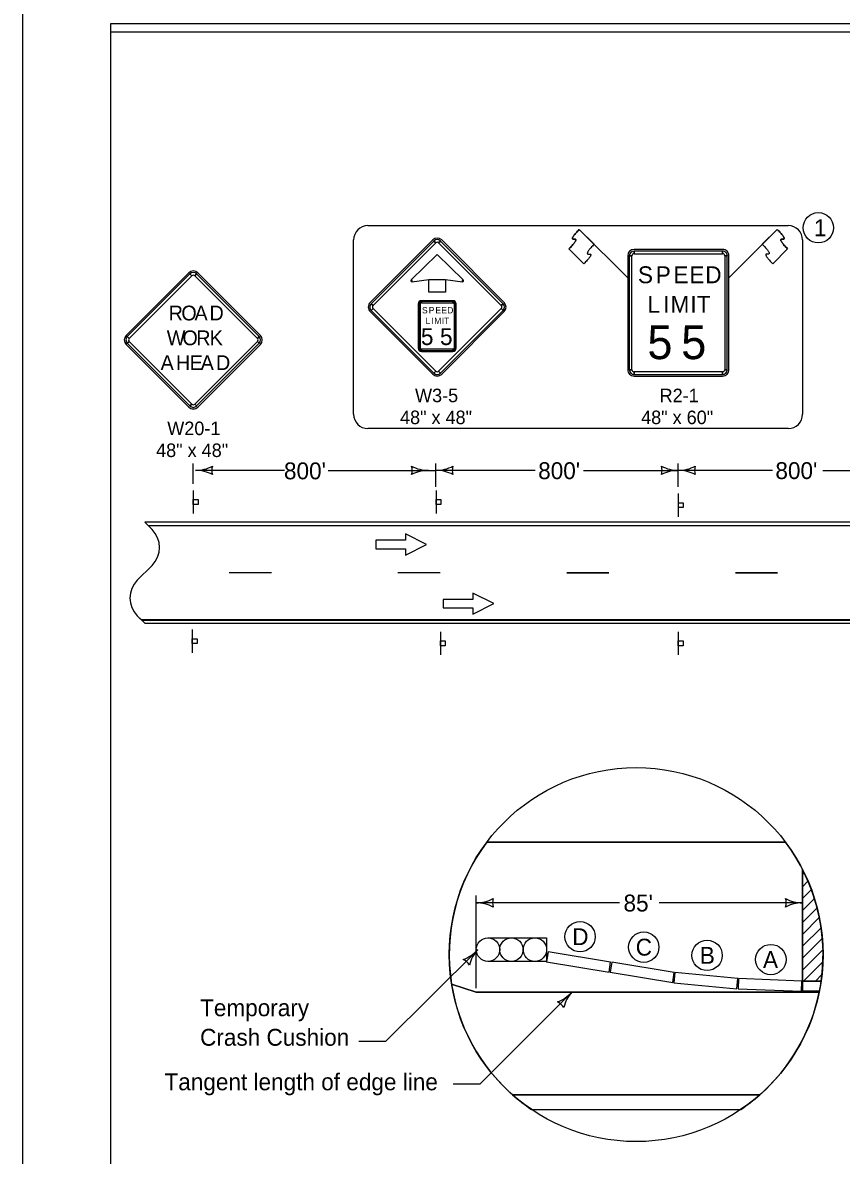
# Model space of a CAD drawing. Extents: x 10133 to 81668, y 4177 to 11018.
# Drawn here: x 24428 to 25399, y 8603 to 9945 of the extents above; entities that cross this region are included whole.
import ezdxf

# ---------------------------------------------------------------- set-up
doc = ezdxf.new("R2010")
doc.units = 0
for name, color, linetype in [('dsnNonPlotable', 7, 'Continuous'), ('dsnStdBlockModified', 7, 'Continuous'), ('dsnStdBorder', 7, 'Continuous'), ('dsnStdDimension', 7, 'Continuous'), ('dsnStdLabel', 7, 'Continuous'), ('dsnStdLineWork', 7, 'Continuous'), ('dsnStdNote', 7, 'Continuous'), ('dsnStdShading', 7, 'Continuous'), ('Level 2', 7, 'Continuous'), ('SheetBorder', 7, 'Continuous')]:
    doc.layers.add(name, color=color, linetype=linetype)

msp = doc.modelspace()

# ---------------------------------------------------------------- linework, layer by layer
at = {"layer": 'dsnNonPlotable'}
for p, q in [((25145.5, 9642.6), (25088.1, 9699.9)), ((25088.1, 9699.9), (25105.8, 9682.3)), ((25265.5, 9642.6), (25322.8, 9699.9)), ((25322.8, 9699.9), (25305.1, 9682.3)), ((24914.3, 9687.5), (24840, 9613.2)), ((24915.6, 9686.1), (24917.8, 9683.9)), ((24921.3, 9683.9), (24923.6, 9686.1)), ((24999.1, 9613.2), (24924.9, 9687.5)), ((25075.8, 9676.9), (25093.4, 9659.3)), ((25093.4, 9659.3), (25075.8, 9676.9)), ((25145.5, 9668.7), (25145.5, 9533.7)), ((25147.3, 9668.7), (25150.5, 9668.7)), ((25258, 9676.2), (25153, 9676.2)), ((25153, 9671.2), (25153, 9674.3)), ((25258, 9674.3), (25258, 9671.2)), ((25260.5, 9668.7), (25263.6, 9668.7)), ((25265.5, 9533.7), (25265.5, 9668.7)), ((25335.1, 9676.9), (25317.5, 9659.3)), ((25317.5, 9659.3), (25335.1, 9676.9)), ((24625.1, 9648.5), (24550.8, 9574.3)), ((24626.4, 9647.2), (24628.6, 9645)), ((24632.1, 9645), (24634.3, 9647.2)), ((24709.9, 9574.3), (24635.7, 9648.5)), ((24889.6, 9639.2), (24888.7, 9640.1)), ((24889.7, 9637.9), (24889.6, 9639.2)), ((24949.6, 9639.2), (24949.4, 9637.9)), ((24950.5, 9640.1), (24949.6, 9639.2)), ((24843.6, 9609.7), (24841.3, 9611.9)), ((24897.1, 9611.7), (24897.1, 9559.2)), ((24898, 9611.7), (24899.6, 9611.7)), ((24938.3, 9615.4), (24900.8, 9615.4)), ((24900.8, 9612.9), (24900.8, 9614.5)), ((24938.3, 9614.5), (24938.3, 9612.9)), ((24939.6, 9611.7), (24941.1, 9611.7)), ((24942.1, 9559.2), (24942.1, 9611.7)), ((24997.8, 9611.9), (24995.6, 9609.7)), ((24840, 9602.6), (24914.3, 9528.4)), ((24841.3, 9603.9), (24843.6, 9606.1)), ((24924.9, 9528.4), (24999.1, 9602.6)), ((24995.6, 9606.1), (24997.8, 9603.9)), ((24554.4, 9570.7), (24552.1, 9572.9)), ((24708.6, 9572.9), (24706.4, 9570.7)), ((24550.8, 9563.6), (24625.1, 9489.4)), ((24552.1, 9565), (24554.4, 9567.2)), ((24635.7, 9489.4), (24709.9, 9563.6)), ((24706.4, 9567.2), (24708.6, 9565)), ((24899.6, 9559.2), (24898, 9559.2)), ((24941.1, 9559.2), (24939.6, 9559.2)), ((24900.8, 9556.4), (24900.8, 9557.9)), ((24900.8, 9555.4), (24938.3, 9555.4)), ((24938.3, 9557.9), (24938.3, 9556.4)), ((24917.8, 9531.9), (24915.6, 9529.7)), ((24923.6, 9529.7), (24921.3, 9531.9)), ((25150.5, 9533.7), (25147.3, 9533.7)), ((25153, 9528), (25153, 9531.2)), ((25258, 9531.2), (25258, 9528)), ((25263.6, 9533.7), (25260.5, 9533.7)), ((25153, 9526.2), (25258, 9526.2)), ((24628.6, 9492.9), (24626.4, 9490.7)), ((24634.3, 9490.7), (24632.1, 9492.9)), ((24630.3, 9390.6), (24630.3, 9363.1)), ((24918.3, 9390.6), (24918.3, 9363.1)), ((25205.5, 9386.8), (25205.5, 9359.3)), ((24629.1, 9225.6), (24629.1, 9198.1)), ((24923.4, 9223.1), (24923.4, 9195.6)), ((25205.5, 9223.1), (25205.5, 9195.6))]:
    msp.add_line(p, q, dxfattribs=at)
for points in [[(24837.4, 9704.6), (25335.8, 9704.6)], [(24820.4, 9480.9), (24820.4, 9687.5)], [(25352.8, 9687.5), (25352.8, 9480.9)], [(25335.8, 9463.9), (24837.4, 9463.9)], [(24846.8, 9331.5), (24846.8, 9321.5), (24881.8, 9321.5), (24881.8, 9314), (24906.8, 9326.5), (24881.8, 9339), (24881.8, 9331.5), (24846.8, 9331.5)], [(24926.8, 9261.5), (24926.8, 9251.5), (24961.8, 9251.5), (24961.8, 9244), (24986.8, 9256.5), (24961.8, 9269), (24961.8, 9261.5), (24926.8, 9261.5)]]:
    msp.add_lwpolyline(points, dxfattribs=at)
for points in [[(24915.6, 9686.1), (24841.3, 9611.9), (24843.6, 9609.7), (24917.8, 9683.9), (24915.6, 9686.1)], [(24997.8, 9611.9), (24923.6, 9686.1), (24921.3, 9683.9), (24995.6, 9609.7), (24997.8, 9611.9)], [(24919.6, 9670.4), (24888.7, 9640.1), (24889.6, 9639.2), (24889.7, 9637.9), (24909.6, 9640.4), (24929.6, 9640.4), (24949.4, 9637.9), (24949.6, 9639.2), (24950.5, 9640.1), (24919.6, 9670.4)], [(25147.3, 9668.7), (25147.3, 9533.7), (25150.5, 9533.7), (25150.5, 9668.7), (25147.3, 9668.7)], [(25258, 9674.3), (25153, 9674.3), (25153, 9671.2), (25258, 9671.2), (25258, 9674.3)], [(25263.6, 9533.7), (25263.6, 9668.7), (25260.5, 9668.7), (25260.5, 9533.7), (25263.6, 9533.7)], [(24626.4, 9647.2), (24552.1, 9572.9), (24554.4, 9570.7), (24628.6, 9645), (24626.4, 9647.2)], [(24708.6, 9572.9), (24634.3, 9647.2), (24632.1, 9645), (24706.4, 9570.7), (24708.6, 9572.9)], [(24929.6, 9625.4), (24909.6, 9625.4), (24909.6, 9640.4), (24929.6, 9640.4), (24929.6, 9625.4)], [(24898, 9611.7), (24898, 9559.2), (24899.6, 9559.2), (24899.6, 9611.7), (24898, 9611.7)], [(24938.3, 9614.5), (24900.8, 9614.5), (24900.8, 9612.9), (24938.3, 9612.9), (24938.3, 9614.5)], [(24941.1, 9559.2), (24941.1, 9611.7), (24939.6, 9611.7), (24939.6, 9559.2), (24941.1, 9559.2)], [(24841.3, 9603.9), (24915.6, 9529.7), (24917.8, 9531.9), (24843.6, 9606.1), (24841.3, 9603.9)], [(24923.6, 9529.7), (24997.8, 9603.9), (24995.6, 9606.1), (24921.3, 9531.9), (24923.6, 9529.7)], [(24552.1, 9565), (24626.4, 9490.7), (24628.6, 9492.9), (24554.4, 9567.2), (24552.1, 9565)], [(24634.3, 9490.7), (24708.6, 9565), (24706.4, 9567.2), (24632.1, 9492.9), (24634.3, 9490.7)], [(24900.8, 9556.4), (24938.3, 9556.4), (24938.3, 9557.9), (24900.8, 9557.9), (24900.8, 9556.4)], [(25153, 9528), (25258, 9528), (25258, 9531.2), (25153, 9531.2), (25153, 9528)], [(24630.4, 9374.1), (24630.4, 9379.7), (24636, 9379.7), (24636, 9374.1)], [(24918.4, 9374.1), (24918.4, 9379.7), (24924, 9379.7), (24924, 9374.1)], [(25205.6, 9370.4), (25205.6, 9376), (25211.2, 9376), (25211.2, 9370.4)], [(24629.2, 9209.1), (24629.2, 9214.8), (24634.8, 9214.8), (24634.8, 9209.1)], [(24923.5, 9206.6), (24923.5, 9212.2), (24929.1, 9212.2), (24929.1, 9206.6)], [(25205.5, 9206.6), (25205.5, 9212.2), (25211.2, 9212.2), (25211.2, 9206.6)]]:
    msp.add_lwpolyline(points, close=True, dxfattribs=at)
for centre, radius in [((25155.5, 8840.5), 221.6), ((24979.8, 8846.4), 13.9), ((25007.6, 8846.4), 13.9), ((25035.4, 8846.4), 13.9)]:
    msp.add_circle(centre, radius, dxfattribs=at)
for centre, radius, start, end in [((24837.4, 9687.5), 17, 90, 180), ((25335.8, 9687.5), 17, 0, 90), ((24919.6, 9682.2), 7.5, 45, 134.9997), ((24919.6, 9682.2), 5.62, 45, 134.9997), ((24919.6, 9682.2), 2.5, 45, 134.9997), ((25153, 9668.7), 7.5, 90.0002, 179.9998), ((25153, 9668.7), 5.62, 90.0002, 179.9998), ((25153, 9668.7), 2.5, 90.0002, 179.9998), ((25258, 9668.7), 7.5, 0, 90.0002), ((25258, 9668.7), 5.62, 0, 90.0002), ((25258, 9668.7), 2.5, 0, 90.0002), ((24630.4, 9643.2), 7.5, 45, 134.9997), ((24630.4, 9643.2), 5.62, 45, 134.9997), ((24630.4, 9643.2), 2.5, 45, 134.9997), ((24889.6, 9639.2), 1.25, 134.9997, 277.1529), ((24949.6, 9639.2), 1.25, 262.8473, 44.9998), ((24845.3, 9607.9), 7.5, 134.9997, 225), ((24845.3, 9607.9), 5.62, 134.9997, 225), ((24900.8, 9611.7), 3.75, 90.0002, 179.9998), ((24900.8, 9611.7), 2.81, 90.0002, 179.9998), ((24900.8, 9611.7), 1.25, 90.0002, 179.9998), ((24938.3, 9611.7), 3.75, 0, 90.0002), ((24938.3, 9611.7), 2.81, 0, 90.0002), ((24938.3, 9611.7), 1.25, 0, 90.0002), ((24993.8, 9607.9), 5.62, 315.0002, 44.9998), ((24993.8, 9607.9), 7.5, 315.0002, 44.9998), ((24845.3, 9607.9), 2.5, 134.9997, 225), ((24993.8, 9607.9), 2.5, 315.0002, 44.9998), ((24556.1, 9568.9), 7.5, 134.9997, 225), ((24556.1, 9568.9), 5.62, 134.9997, 225), ((24704.6, 9568.9), 5.62, 315.0002, 44.9998), ((24704.6, 9568.9), 7.5, 315.0002, 44.9998), ((24556.1, 9568.9), 2.5, 134.9997, 225), ((24704.6, 9568.9), 2.5, 315.0002, 44.9998), ((24900.8, 9559.2), 3.75, 179.9998, 270.0001), ((24900.8, 9559.2), 2.81, 179.9998, 270.0001), ((24900.8, 9559.2), 1.25, 179.9998, 270.0001), ((24938.3, 9559.2), 3.75, 270.0001, 0.0003), ((24938.3, 9559.2), 2.81, 270.0001, 0.0003), ((24938.3, 9559.2), 1.25, 270.0001, 0.0003), ((24919.6, 9533.7), 2.5, 225, 315.0002), ((25153, 9533.7), 7.5, 179.9998, 270.0001), ((25153, 9533.7), 5.62, 179.9998, 270.0001), ((25153, 9533.7), 2.5, 179.9998, 270.0001), ((25258, 9533.7), 7.5, 270.0001, 0.0003), ((25258, 9533.7), 5.62, 270.0001, 0.0003), ((25258, 9533.7), 2.5, 270.0001, 0.0003), ((24919.6, 9533.7), 7.5, 225, 315.0002), ((24919.6, 9533.7), 5.62, 225, 315.0002), ((24630.4, 9494.7), 2.5, 225, 315.0002), ((24630.4, 9494.7), 7.5, 225, 315.0002), ((24630.4, 9494.7), 5.62, 225, 315.0002), ((24837.4, 9480.9), 17, 180, 270), ((25335.8, 9480.9), 17, 270, 0)]:
    msp.add_arc(centre, radius, start, end, dxfattribs=at)
for points in [[(25088.1, 9699.9), (25075.8, 9687.6), (25088.1, 9689.3), (25075.8, 9676.9)], [(25075.8, 9676.9), (25088.1, 9689.3), (25075.8, 9687.6), (25088.1, 9699.9)], [(25322.8, 9699.9), (25335.1, 9687.6), (25322.8, 9689.3), (25335.1, 9676.9)], [(25335.1, 9676.9), (25322.8, 9689.3), (25335.1, 9687.6), (25322.8, 9699.9)], [(25105.8, 9682.3), (25093.4, 9669.9), (25105.8, 9671.6), (25093.4, 9659.3)], [(25105.8, 9682.3), (25093.4, 9669.9), (25105.8, 9671.6), (25093.4, 9659.3)], [(25305.1, 9682.3), (25317.5, 9669.9), (25305.1, 9671.6), (25317.5, 9659.3)], [(25305.1, 9682.3), (25317.5, 9669.9), (25305.1, 9671.6), (25317.5, 9659.3)]]:
    msp.add_open_spline(points, degree=2, dxfattribs=at)
at = {"layer": 'dsnStdBlockModified'}
msp.add_lwpolyline([(24532.5, 9934), (27667.5, 9934), (27667.5, 7924), (24532.5, 7924)], close=True, dxfattribs=at)
at = {"layer": 'dsnStdBorder'}
msp.add_lwpolyline([(24428, 7819.5), (27772, 7819.5), (27772, 10403.5), (24428, 10403.5)], close=True, dxfattribs=at)
at = {"layer": 'dsnStdDimension'}
for p, q in [((25617.2, 9353.1), (24572.8, 9353.1)), ((24572.8, 9353.1), (24581.6, 9344.3)), ((25609.9, 9353.1), (24572.8, 9353.1)), ((24576.8, 9349.1), (25609.9, 9349.1)), ((24581.6, 9301.8), (24564, 9284.3)), ((24564, 9241.8), (24568.8, 9237.1)), ((26364.3, 9237.1), (24568.8, 9237.1)), ((24568.8, 9237.1), (24572.8, 9233.1)), ((24568.8, 9237.1), (25786, 9237.1)), ((24572.8, 9233.1), (26391.1, 9233.1)), ((24572.8, 9233.1), (26362.6, 9233.1)), ((25332.4, 8973.9), (24978.5, 8973.9)), ((25352.6, 8809.1), (25374.8, 8809.1)), ((24936.6, 8805.5), (24965.9, 8796.1)), ((24965.9, 8796.1), (24936.6, 8805.5)), ((24965.9, 8796.1), (25372.6, 8796.1)), ((25372.6, 8796.1), (24965.9, 8796.1)), ((25008.9, 8674.3), (25302, 8674.3)), ((25302, 8674.3), (25008.9, 8674.3)), ((25031.2, 8657), (25279.7, 8657))]:
    msp.add_line(p, q, dxfattribs=at)
for points in [[(24572.8, 9353.1), (24576.8, 9349.1), (24576.8, 9349.1)], [(24568.8, 9237.1), (24568.8, 9237.1)], [(24568.8, 9237.1), (24568.8, 9237.1)], [(25352.6, 8941.6), (25352.6, 8901.9), (25352.6, 8809.1)], [(25125.2, 8831.6), (25051.2, 8843.7), (25049.3, 8831.9), (25123.3, 8819.8), (25125.2, 8831.6)], [(25200.7, 8819.2), (25126.7, 8831.4), (25124.8, 8819.5), (25198.8, 8807.4), (25200.7, 8819.2)], [(25276.1, 8812), (25201.5, 8819.1), (25200.3, 8807.2), (25275, 8800.1), (25276.1, 8812)], [(25351.9, 8809.1), (25277, 8812.1), (25276.5, 8800.1), (25351.4, 8797.1), (25351.9, 8809.1)], [(25374.8, 8809.1), (25352.6, 8809.1), (25352.6, 8797.1), (25372.8, 8797.1)], [(25372.8, 8797.1), (25352.6, 8797.1), (25352.6, 8809.1), (25374.8, 8809.1)]]:
    msp.add_lwpolyline(points, dxfattribs=at)
for centre, radius, start, end in [((24560.3, 9323), 30, 315, 45), ((24585.2, 9263.1), 30, 135, 225), ((25155.5, 8840.5), 221.6, 142.9773, 189.0659), ((25155.5, 8840.5), 221.6, 351.8621, 37.0227), ((25155.5, 8840.5), 221.6, 351.8621, 27.1505), ((25155.5, 8840.5), 221.6, 348.7138, 351.8621), ((25155.5, 8840.5), 221.6, 189.0659, 228.5906), ((25155.5, 8840.5), 221.6, 311.4094, 348.45), ((25155.5, 8840.5), 221.6, 348.45, 348.7138), ((25155.5, 8840.5), 221.6, 228.5906, 235.889), ((25155.5, 8840.5), 221.6, 304.111, 311.4094)]:
    msp.add_arc(centre, radius, start, end, dxfattribs=at)
at = {"layer": 'dsnStdLabel'}
for p, q in [((24581.6, 9344.3), (24572.8, 9353)), ((24576.8, 9349.1), (26185, 9349.1)), ((24564, 9284.3), (24581.6, 9301.8)), ((24572.8, 9233.1), (24564, 9241.8)), ((24568.8, 9237), (26597.2, 9237)), ((24978.5, 8973.9), (25332.4, 8973.9)), ((25352.6, 8809.1), (25352.6, 8941.6)), ((25352.6, 8935.1), (25354.8, 8937.3)), ((25352.6, 8921), (25359.2, 8927.5)), ((25352.6, 8906.8), (25363.2, 8917.4)), ((25352.6, 8892.7), (25366.9, 8906.9)), ((25352.6, 8878.5), (25370, 8895.9)), ((25352.6, 8864.4), (25372.6, 8884.4)), ((25352.6, 8850.3), (25374.7, 8872.4)), ((25352.6, 8836.1), (25376.2, 8859.7)), ((25352.6, 8822), (25377, 8846.3)), ((25353.9, 8809.1), (25376.9, 8832.1)), ((25368, 8809.1), (25375.8, 8816.8)), ((24936.6, 8805.5), (24965.9, 8796.1)), ((24965.9, 8796.1), (25372.6, 8796.1)), ((25008.9, 8674.3), (25302, 8674.3))]:
    msp.add_line(p, q, dxfattribs=at)
for points in [[(24673.1, 9293.5), (24723.1, 9293.5)], [(24873.1, 9293.5), (24923.1, 9293.5)], [(25073.1, 9293.5), (25123.1, 9293.5)], [(25073.1, 9293.1), (25123.1, 9293.1)], [(25273.1, 9293.5), (25323, 9293.5)], [(25273.1, 9293.1), (25323, 9293.1)], [(25372.8, 8797.1), (25352.6, 8797.1), (25352.6, 8809.1), (25374.8, 8809.1)]]:
    msp.add_lwpolyline(points, dxfattribs=at)
for points in [[(25125.2, 8831.6), (25051.2, 8843.7), (25049.3, 8831.9), (25123.3, 8819.8)], [(25200.7, 8819.2), (25126.7, 8831.4), (25124.8, 8819.5), (25198.8, 8807.4)], [(25276.1, 8812), (25201.5, 8819.1), (25200.3, 8807.2), (25275, 8800.1)], [(25351.9, 8809.1), (25277, 8812.1), (25276.5, 8800.1), (25351.4, 8797.1)]]:
    msp.add_lwpolyline(points, close=True, dxfattribs=at)
for centre, start, end in [((24560.3, 9323), 315, 45), ((24585.2, 9263.1), 135, 225)]:
    msp.add_arc(centre, 30, start, end, dxfattribs=at)
at = {"layer": 'dsnStdLineWork'}
for p, q in [((24979.8, 8860.3), (25049.3, 8860.3)), ((25049.3, 8860.3), (25049.3, 8832.5)), ((25049.3, 8832.5), (24979.8, 8832.5)), ((25048.7, 8831.2), (25048.7, 8831.2))]:
    msp.add_line(p, q, dxfattribs=at)
for centre in [(24979.8, 8846.4), (24979.8, 8846.4), (25007.6, 8846.4), (25007.6, 8846.4), (25035.4, 8846.4), (25035.4, 8846.4)]:
    msp.add_circle(centre, 13.9, dxfattribs=at)
at = {"layer": 'dsnStdNote'}
for p, q in [((24630.3, 9398.6), (24630.3, 9422.6)), ((24738.5, 9414.4), (24633.1, 9414.4)), ((24790.4, 9414.4), (24917.9, 9414.4)), ((24917.9, 9394.8), (24917.9, 9422.6)), ((25035.6, 9414.4), (24917.9, 9414.4)), ((25093, 9414.4), (25205.5, 9414.4)), ((25205.5, 9394.8), (25205.5, 9422.6)), ((25317.2, 9414.4), (25205.5, 9414.4)), ((25376.7, 9414.4), (25493.1, 9414.4)), ((24965.9, 8800.6), (24965.9, 8910.6)), ((25135.9, 8901.9), (24965.9, 8901.9)), ((25352.6, 8901.9), (25182.6, 8901.9)), ((25352.6, 8813.6), (25352.6, 8910.6)), ((24967.6, 8846.3), (24858.7, 8737.8)), ((25079.3, 8796), (24970.4, 8687.4)), ((24826.7, 8737.8), (24858.7, 8737.8)), ((24938.4, 8687.4), (24970.4, 8687.4))]:
    msp.add_line(p, q, dxfattribs=at)
for centre, radius, start, end in [((24633.1, 9456.9), 42.5, 270, 298.0725), ((24633.1, 9371.9), 42.5, 61.9275, 90), ((24668.7, 9414.4), 16.4, 162.2666, 197.7334), ((24873.5, 9414.4), 16.4, 342.2666, 17.7334), ((24909.2, 9456.9), 42.5, 241.9275, 270), ((24909.2, 9371.9), 42.5, 90, 118.0725), ((24918.3, 9456.9), 42.5, 270, 298.0725), ((24918.3, 9371.9), 42.5, 61.9275, 90), ((24953.9, 9414.4), 16.4, 162.2666, 197.7334), ((25169.8, 9414.4), 16.4, 342.2666, 17.7334), ((25205.5, 9456.9), 42.5, 241.9275, 270), ((25205.5, 9371.9), 42.5, 90, 118.0725), ((25205.5, 9456.9), 42.5, 270, 298.0725), ((25205.5, 9371.9), 42.5, 61.9275, 90), ((25241.1, 9414.4), 16.4, 162.2666, 197.7334), ((24965.9, 8944.4), 42.5, 270, 298.0725), ((24965.9, 8859.4), 42.5, 61.9275, 90), ((25001.6, 8901.9), 16.4, 162.2666, 197.7334), ((25317, 8901.9), 16.4, 342.2666, 17.7334), ((25352.6, 8944.4), 42.5, 241.9275, 270), ((25352.6, 8859.4), 42.5, 90, 118.0725), ((24935.6, 8874.5), 42.5, 290.4723, 318.5448), ((24943.8, 8819.7), 16.4, 30.8115, 66.2782), ((24999.3, 8818.3), 42.5, 138.5448, 166.6173), ((25047.3, 8824.2), 42.5, 290.4723, 318.5448), ((25111, 8768), 42.5, 138.5448, 166.6173), ((25055.5, 8769.4), 16.4, 30.8115, 66.2782)]:
    msp.add_arc(centre, radius, start, end, dxfattribs=at)
at = {"layer": 'dsnStdShading'}
msp.add_line((25352.6, 8813.6), (25352.6, 8910.6), dxfattribs=at)
at = {"layer": 'Level 2'}
for centre in [(25371.5, 9701.9), (25089, 8861.7), (25164.5, 8849.3), (25239.6, 8839.6), (25315.2, 8834.6)]:
    msp.add_circle(centre, 18, dxfattribs=at)
at = {"layer": 'SheetBorder'}
msp.add_lwpolyline([(24532.5, 9944), (27667.5, 9944), (27667.5, 7924), (24532.5, 7924)], close=True, dxfattribs=at)

# ---------------------------------------------------------------- texts
at = {"layer": 'dsnNonPlotable'}
for s, height, p in [('S', 20, (25157.6, 9636.2)), ('P', 20, (25178.7, 9636.2)), ('E', 20, (25199.8, 9636.2)), ('E', 20, (25218.6, 9636.2)), ('D', 20, (25237.4, 9636.2)), ('L', 20, (25168.8, 9601.2)), ('I', 20, (25187.6, 9601.2)), ('M', 20, (25196.2, 9601.2)), ('I', 20, (25219.8, 9601.2)), ('T', 20, (25227.4, 9601.2)), ('R', 17.5, (24601.2, 9592.1)), ('O', 17.5, (24616.2, 9592.1)), ('A', 17.5, (24631.8, 9592.1)), ('D', 17.5, (24649.6, 9592.1)), ('S', 7.5, (24901.6, 9600.4)), ('P', 7.5, (24909.5, 9600.4)), ('E', 7.5, (24917.4, 9600.4)), ('E', 7.5, (24924.5, 9600.4)), ('D', 7.5, (24931.5, 9600.4)), ('L', 7.5, (24905.8, 9587.9)), ('I', 7.5, (24912.9, 9587.9)), ('M', 7.5, (24916.1, 9587.9)), ('I', 7.5, (24925, 9587.9)), ('T', 7.5, (24927.8, 9587.9)), ('5', 40, (25168.8, 9546.2)), ('5', 40, (25208.9, 9546.2)), ('W', 17.5, (24598.9, 9562.7)), ('O', 17.5, (24617.5, 9562.7)), ('R', 17.5, (24633.9, 9562.7)), ('K', 17.5, (24649.8, 9562.7)), ('5', 20, (24900.3, 9562.9)), ('5', 20, (24922.9, 9562.9)), ('A', 17.5, (24591.6, 9533.3)), ('H', 17.5, (24609.9, 9533.3)), ('E', 17.5, (24626.1, 9533.3)), ('A', 17.5, (24639.1, 9533.3)), ('D', 17.5, (24657.3, 9533.3)), ('W3-5', 16, (24893.3, 9495.2)), ('R2-1', 16, (25183.3, 9495.2)), ('48" x 48"', 16, (24875.5, 9469.2)), ('48" x 60"', 16, (25161.4, 9469.2)), ('W20-1', 16, (24599.5, 9456.2)), ('48" x 48"', 16, (24586.3, 9430.2))]:
    msp.add_text(s, height=height, dxfattribs=at).set_placement(p)
at = {"layer": 'dsnStdNote'}
for s, p in [("800'", (24737.9, 9403.8)), ("800'", (25039.3, 9404)), ("800'", (25320.6, 9404.1)), ("85'", (25140.5, 8891.6)), ('Temporary ', (24638.4, 8767.5)), ('Crash Cushion', (24638.4, 8732.5)), ('Tangent length of edge line', (24596.2, 8679.7))]:
    msp.add_text(s, height=20, dxfattribs=at).set_placement(p)
at = {"layer": 'Level 2'}
for s, p in [('1', (25366.3, 9691.9)), ('D', (25079.7, 8851.7)), ('C', (25155, 8839.3)), ('B', (25231, 8829.6)), ('A', (25305.9, 8824.6))]:
    msp.add_text(s, height=20, dxfattribs=at).set_placement(p)

doc.saveas('drawing.dxf')
